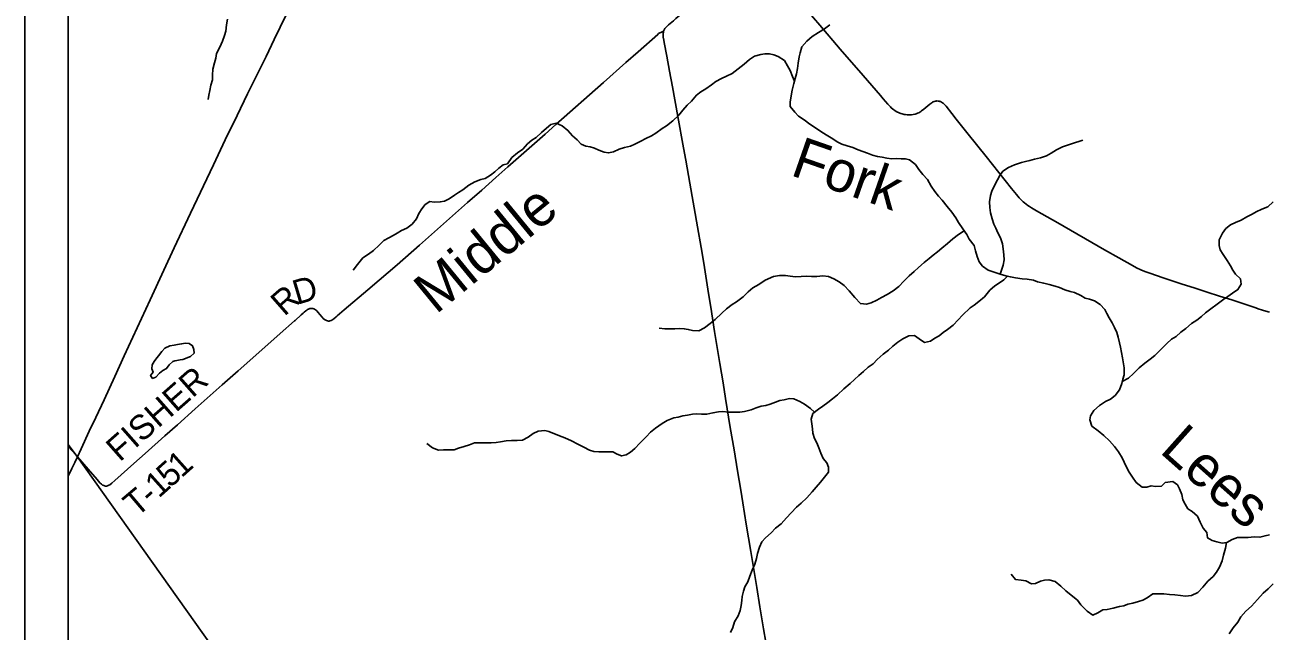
# Model space of a CAD drawing. Extents: x 0 to 34, y 0 to 22.
# Drawn here: x 2 to 4.871, y 16.697 to 18.098 of the extents above; entities that cross this region are included whole.
import ezdxf

# ---------------------------------------------------------------- set-up
doc = ezdxf.new("R2010")
doc.units = 0
for name, color, linetype in [('Default', 7, 'Continuous'), ('GM_X_County_Road', 7, 'Continuous'), ('GM_X_Minor_Lake', 7, 'Continuous'), ('GM_X_Minor_River', 7, 'Continuous'), ('GM_X_Minor_River_Text', 7, 'Continuous'), ('GM_X_State_Route', 7, 'Continuous'), ('GM_X_Township_Road', 7, 'Continuous'), ('GM_X_Township_Road_Text', 7, 'Continuous'), ('SH_Cut_Line', 7, 'Continuous'), ('SH_Data', 7, 'Continuous')]:
    doc.layers.add(name, color=color, linetype=linetype)

msp = doc.modelspace()

# ---------------------------------------------------------------- linework, layer by layer
at = {"layer": 'Default'}
msp.add_lwpolyline([(6.6858, 19.0362), (6.6949, 19.1537), (6.8302, 20.9), (3.1229, 20.9), (2.9275, 20.8467), (2.2946, 20.6707), (2.1, 20.6202), (2.1, 17.1279), (2.1211, 17.1003), (3.2076, 15.5689), (3.4902, 15.1704), (4.0558, 14.3671), (4.1658, 14.2105), (4.302, 14.3105), (5.6165, 15.2674), (6.0871, 15.6176), (6.2834, 15.7529), (6.4392, 15.8657), (6.5428, 17.1931), (6.5451, 17.2211), (6.6309, 18.3364), (6.6363, 18.3979), (6.6654, 18.7733)], dxfattribs=at)
msp.add_lwpolyline([(2.1, 17.1279), (2.1, 14.1), (4.022, 14.1), (4.1658, 14.2105), (4.0558, 14.3671), (3.4902, 15.1704), (3.2076, 15.5689), (2.1211, 17.1003)], close=True, dxfattribs=at)
at = {"layer": 'GM_X_County_Road'}
for points in [[(3.4749, 18.0827), (3.4756, 18.0847), (3.4764, 18.0862), (3.4771, 18.0877), (3.4779, 18.0888), (3.4786, 18.0899), (3.4795, 18.091), (3.4808, 18.0924), (3.4827, 18.0944), (3.4864, 18.0979), (3.4902, 18.1011), (3.4974, 18.1071), (3.5031, 18.1119), (3.5555, 18.1568), (3.5751, 18.174), (3.6216, 18.2143), (3.6711, 18.2567), (3.6866, 18.27)], [(4.8734, 17.4339), (4.8656, 17.4358), (4.8573, 17.4384), (4.8478, 17.4416), (4.842, 17.4436), (4.7865, 17.4619), (4.7586, 17.4707), (4.7297, 17.4801), (4.6996, 17.4898), (4.6724, 17.4987), (4.647, 17.507), (4.6281, 17.5132), (4.5976, 17.5236), (4.5859, 17.5279), (4.5768, 17.5316), (4.5666, 17.5363), (4.5573, 17.5412), (4.526, 17.5589), (4.4926, 17.5781), (4.3848, 17.6399), (4.3358, 17.6682), (4.3241, 17.6751), (4.32, 17.6777), (4.3158, 17.6805), (4.3119, 17.6834), (4.3084, 17.686), (4.3053, 17.6888), (4.302, 17.6918), (4.2989, 17.695), (4.296, 17.698), (4.2895, 17.7055), (4.2782, 17.7195), (4.249, 17.7566), (4.2193, 17.7933), (4.1782, 17.8447), (4.1505, 17.8798), (4.1404, 17.8924), (4.1269, 17.9095), (4.1249, 17.9118), (4.1236, 17.9133), (4.1223, 17.9147), (4.1205, 17.9163), (4.119, 17.9177), (4.1167, 17.919), (4.1144, 17.9202), (4.1129, 17.9207), (4.1113, 17.9212), (4.1088, 17.9216), (4.1055, 17.9218), (4.1038, 17.9216), (4.1023, 17.9213), (4.0998, 17.9206), (4.0974, 17.9195), (4.0959, 17.9187), (4.0942, 17.9175), (4.0897, 17.9141), (4.0758, 17.9025), (4.0705, 17.8986), (4.0689, 17.8974), (4.0665, 17.896), (4.0641, 17.8947), (4.0608, 17.8932), (4.0582, 17.8922), (4.0556, 17.8914), (4.0509, 17.8903), (4.0475, 17.8898), (4.0445, 17.8895), (4.0419, 17.8895), (4.0393, 17.8896), (4.0369, 17.8898), (4.0337, 17.8902), (4.0302, 17.8907), (4.0281, 17.8911), (4.0254, 17.8918), (4.0229, 17.8925), (4.0201, 17.8934), (4.0168, 17.8948), (4.0145, 17.8959), (4.0119, 17.8972), (4.0087, 17.8994), (4.0063, 17.901), (4.003, 17.9037), (4.0002, 17.9062), (3.9985, 17.9079), (3.9922, 17.9147), (3.9821, 17.9265), (3.9756, 17.934), (3.9359, 17.9802), (3.8827, 18.0418), (3.8358, 18.0965), (3.8061, 18.1308)], [(3.7107, 16.671), (3.7056, 16.7017), (3.6973, 16.7526), (3.6899, 16.7973), (3.6762, 16.8807), (3.6658, 16.9439), (3.6576, 16.9935), (3.6528, 17.0223), (3.6456, 17.0671), (3.6375, 17.1155), (3.6287, 17.1676), (3.6179, 17.2344), (3.6122, 17.2706), (3.6049, 17.3154), (3.5965, 17.3663), (3.5927, 17.389), (3.5887, 17.4148), (3.5854, 17.4356), (3.577, 17.4865), (3.5674, 17.5466), (3.5612, 17.5828), (3.5533, 17.6312), (3.5354, 17.7321), (3.526, 17.7847), (3.5209, 17.8135), (3.5078, 17.8856), (3.4954, 17.9541), (3.4887, 17.9907), (3.4822, 18.0249), (3.4762, 18.0567), (3.4751, 18.0622), (3.474, 18.0691), (3.4738, 18.0717), (3.4736, 18.0742), (3.4737, 18.0766), (3.4739, 18.0786), (3.4742, 18.0804), (3.4746, 18.0818), (3.4749, 18.0827)]]:
    msp.add_lwpolyline(points, dxfattribs=at)
at = {"layer": 'GM_X_Minor_Lake'}
for points in [[(2.316, 17.3428), (2.3083, 17.333), (2.3021, 17.3255), (2.2986, 17.3194), (2.294, 17.3119), (2.2935, 17.3028), (2.2964, 17.2948), (2.2902, 17.2872), (2.2947, 17.2807), (2.3024, 17.2837), (2.3105, 17.2927), (2.3182, 17.2987), (2.3273, 17.3035), (2.3335, 17.3118), (2.342, 17.3201), (2.3466, 17.321)], [(2.3466, 17.321), (2.3512, 17.3219), (2.3588, 17.3233), (2.3649, 17.3244), (2.3825, 17.331), (2.3906, 17.3393), (2.3903, 17.3473), (2.3869, 17.356), (2.3794, 17.3614), (2.371, 17.3623), (2.3619, 17.3605), (2.3527, 17.3591), (2.3444, 17.3573), (2.3348, 17.3562), (2.3233, 17.3507), (2.316, 17.3428)]]:
    msp.add_lwpolyline(points, dxfattribs=at)
at = {"layer": 'GM_X_Minor_River'}
for points in [[(2.4676, 18.1111), (2.4659, 18.0975), (2.4639, 18.0834), (2.4611, 18.0732), (2.4567, 18.06), (2.4501, 18.0464), (2.4423, 18.0316), (2.4406, 18.021), (2.4382, 18.01), (2.4343, 17.9952), (2.4333, 17.9816), (2.4336, 17.9706), (2.4292, 17.9585), (2.4268, 17.9456), (2.4248, 17.935), (2.4231, 17.9251)], [(3.8655, 17.8344), (3.8538, 17.8413), (3.8398, 17.8495), (3.8281, 17.858), (3.8126, 17.8684), (3.7994, 17.878), (3.7859, 17.8866), (3.7776, 17.8961), (3.7671, 17.9088), (3.7672, 17.9191), (3.7693, 17.9335), (3.7717, 17.9467), (3.7754, 17.9619), (3.7785, 17.9736), (3.7817, 17.9846), (3.7838, 17.9971), (3.7854, 18.0093), (3.7879, 18.0237), (3.7903, 18.0331), (3.7943, 18.0472), (3.8058, 18.0596), (3.8181, 18.0704), (3.8327, 18.0802), (3.8461, 18.0884), (3.8588, 18.0977)], [(3.7769, 17.9678), (3.7721, 17.9786), (3.767, 17.992), (3.761, 18.0031), (3.7536, 18.0153), (3.7396, 18.0246), (3.729, 18.0281), (3.7191, 18.0309), (3.7088, 18.031), (3.6993, 18.0292), (3.6848, 18.0256), (3.6729, 18.0174), (3.661, 18.0065), (3.6468, 17.9956), (3.633, 17.9855), (3.62, 17.9792), (3.6081, 17.9737), (3.5951, 17.9666), (3.5855, 17.9591), (3.5724, 17.9501), (3.5605, 17.943), (3.5506, 17.9348), (3.5394, 17.9212), (3.529, 17.9122), (3.5193, 17.9002), (3.5101, 17.8893), (3.4962, 17.8761), (3.4816, 17.8642), (3.4716, 17.8582), (3.4567, 17.847), (3.4471, 17.841), (3.4337, 17.8347), (3.4226, 17.8291), (3.4084, 17.822), (3.3985, 17.8172), (3.3844, 17.8143), (3.3721, 17.8107), (3.3591, 17.8044), (3.3477, 17.8018), (3.3374, 17.8031), (3.3253, 17.8078), (3.3155, 17.8125), (3.3056, 17.8156), (3.2954, 17.8176), (3.2844, 17.8223), (3.275, 17.8319), (3.2645, 17.8415), (3.254, 17.8538), (3.2408, 17.8646), (3.2271, 17.8704), (3.2146, 17.8675), (3.2046, 17.8589), (3.1926, 17.8488), (3.1807, 17.8375), (3.1707, 17.8308), (3.1608, 17.8229), (3.1499, 17.8105), (3.1373, 17.8019), (3.1246, 17.7911), (3.1142, 17.7767), (3.1046, 17.7738), (3.0946, 17.7663), (3.085, 17.7581), (3.075, 17.7502), (3.0628, 17.7424), (3.0528, 17.7402), (3.0391, 17.735), (3.0253, 17.7268), (3.0115, 17.7167), (3.0015, 17.71), (2.9919, 17.7037), (2.9796, 17.6958), (2.9689, 17.6902), (2.959, 17.6885), (2.9453, 17.6882), (2.935, 17.6891), (2.9243, 17.6828), (2.9166, 17.6726), (2.9096, 17.662), (2.9041, 17.6496), (2.8941, 17.6368), (2.8818, 17.6282), (2.8696, 17.6226), (2.8596, 17.6166), (2.85, 17.611), (2.8404, 17.6058), (2.8289, 17.5991), (2.8182, 17.5882), (2.8047, 17.5766), (2.7932, 17.568), (2.7805, 17.559), (2.7682, 17.544), (2.7581, 17.5308)], [(4.6331, 17.0405), (4.6243, 17.0318), (4.6102, 17.0308), (4.6007, 17.0321), (4.5908, 17.0295), (4.5801, 17.0297), (4.5658, 17.0405), (4.5572, 17.0523), (4.5501, 17.0638), (4.5445, 17.0741), (4.5382, 17.0875), (4.5334, 17.0974), (4.5248, 17.1112), (4.5158, 17.1235), (4.5042, 17.1365), (4.491, 17.1484), (4.4782, 17.1592), (4.4635, 17.1704), (4.4588, 17.1849), (4.4604, 17.1944), (4.4678, 17.2064), (4.4816, 17.2184), (4.495, 17.227), (4.5069, 17.233), (4.5173, 17.2412), (4.5273, 17.2544), (4.5328, 17.2692), (4.5352, 17.279), (4.538, 17.2889), (4.5382, 17.3052), (4.5368, 17.3147), (4.5347, 17.328), (4.5318, 17.3402), (4.5297, 17.3531), (4.5271, 17.3627), (4.5242, 17.376), (4.5213, 17.3871), (4.5157, 17.3981), (4.5102, 17.4088), (4.5035, 17.4207), (4.4983, 17.4306), (4.4934, 17.4402), (4.4825, 17.4517), (4.4697, 17.4598), (4.458, 17.4641), (4.4485, 17.4661), (4.4379, 17.472), (4.4235, 17.479), (4.4133, 17.4817), (4.4015, 17.4853), (4.3886, 17.4904), (4.3788, 17.4939), (4.3648, 17.4978), (4.3526, 17.5006), (4.3382, 17.5042), (4.3287, 17.5074), (4.3143, 17.5098), (4.3029, 17.5107), (4.287, 17.5132), (4.2756, 17.5152), (4.2646, 17.5176), (4.2517, 17.5215), (4.2358, 17.5267), (4.224, 17.531), (4.2112, 17.5402), (4.2033, 17.5498), (4.1989, 17.5624), (4.1953, 17.5757), (4.192, 17.5879), (4.1807, 17.6021), (4.1748, 17.6132), (4.1658, 17.6266), (4.1557, 17.6411), (4.1498, 17.6519), (4.1404, 17.6649), (4.1295, 17.6779), (4.1183, 17.6925), (4.1093, 17.7021), (4.101, 17.7124), (4.0928, 17.7251), (4.0843, 17.74), (4.0734, 17.7522), (4.0644, 17.7634), (4.0561, 17.7749), (4.0426, 17.786), (4.0331, 17.788), (4.0236, 17.7881), (4.0122, 17.7886), (4.0015, 17.7884), (3.9901, 17.7897), (3.9795, 17.7917), (3.9689, 17.7937), (3.9575, 17.7965), (3.9454, 17.8012), (3.9351, 17.8051), (3.9242, 17.8086), (3.9117, 17.8141), (3.8988, 17.818), (3.8866, 17.8216), (3.8757, 17.8274), (3.8655, 17.8344)], [(4.2518, 17.5215), (4.2544, 17.5283), (4.2588, 17.5427), (4.2608, 17.5549), (4.2606, 17.5663), (4.2592, 17.58), (4.2575, 17.5918), (4.2527, 17.6055), (4.2468, 17.6173), (4.2419, 17.6276), (4.2375, 17.6372), (4.2338, 17.6494), (4.2298, 17.6635), (4.2281, 17.6757), (4.2275, 17.689), (4.2299, 17.7034), (4.2327, 17.7132), (4.2405, 17.7295), (4.246, 17.7397), (4.2514, 17.7495), (4.2584, 17.7593), (4.271, 17.7683), (4.2848, 17.7742), (4.3008, 17.7793), (4.3104, 17.7822), (4.3207, 17.7844), (4.331, 17.787), (4.3451, 17.7902), (4.3592, 17.795), (4.37, 17.8009), (4.3822, 17.8092), (4.3956, 17.8155), (4.4071, 17.8199), (4.4166, 17.8228), (4.4426, 17.8309)], [(4.6371, 17.3617), (4.6472, 17.3711), (4.6579, 17.3779), (4.6694, 17.3877), (4.6808, 17.3963), (4.6938, 17.4076), (4.7061, 17.4155), (4.7164, 17.4234), (4.7263, 17.4324), (4.7385, 17.4414), (4.7527, 17.452), (4.768, 17.4636), (4.7779, 17.47), (4.7886, 17.4775), (4.8008, 17.4858), (4.8081, 17.4986), (4.8067, 17.5108), (4.7954, 17.5215), (4.789, 17.531), (4.7838, 17.5406), (4.7759, 17.5528), (4.7665, 17.5673), (4.7601, 17.5779), (4.7572, 17.5878), (4.7577, 17.6007), (4.7654, 17.6162), (4.7727, 17.6268), (4.7834, 17.6358), (4.7952, 17.6411), (4.8085, 17.6463), (4.8215, 17.6538), (4.8337, 17.6605), (4.8432, 17.6654), (4.8562, 17.6714), (4.8699, 17.677), (4.8822, 17.689)], [(4.1689, 17.622), (4.1554, 17.6134), (4.1427, 17.6029), (4.1304, 17.5924), (4.117, 17.5819), (4.107, 17.5733), (4.0974, 17.5654), (4.0878, 17.558), (4.0766, 17.5486), (4.0632, 17.5366), (4.0535, 17.5276), (4.042, 17.5174), (4.0293, 17.5051), (4.0177, 17.4934), (4.0051, 17.4833), (3.9909, 17.4747), (3.9779, 17.468), (3.9671, 17.4617), (3.9537, 17.455), (3.9434, 17.4525), (3.9294, 17.4534), (3.9162, 17.4676), (3.9035, 17.4829), (3.8918, 17.4952), (3.8805, 17.5041), (3.8677, 17.5107), (3.8552, 17.5158), (3.8423, 17.5178), (3.8289, 17.5164), (3.816, 17.5162), (3.8053, 17.5171), (3.7928, 17.5165), (3.7791, 17.5155), (3.7669, 17.5171), (3.7559, 17.5184), (3.7422, 17.5182), (3.7285, 17.5164), (3.7094, 17.5075), (3.6944, 17.4978), (3.681, 17.4896), (3.6702, 17.481), (3.6583, 17.469), (3.6433, 17.4577), (3.6334, 17.4518), (3.6199, 17.4417), (3.6091, 17.4311), (3.5937, 17.4169), (3.5822, 17.4075), (3.5692, 17.3974), (3.5558, 17.3907), (3.5417, 17.3916), (3.5318, 17.3937), (3.5223, 17.3953), (3.5117, 17.3958), (3.501, 17.3955), (3.4877, 17.3949), (3.4774, 17.3954), (3.4645, 17.3967)], [(4.2686, 17.5167), (4.2606, 17.5081), (4.2507, 17.5014), (4.2396, 17.4943), (4.228, 17.4842), (4.2157, 17.4695), (4.203, 17.4586), (4.1918, 17.4497), (4.1823, 17.4437), (4.1653, 17.4268), (4.1549, 17.4159), (4.1433, 17.4039), (4.1303, 17.3937), (4.1203, 17.3866), (4.1107, 17.3791), (4.1007, 17.3736), (4.0912, 17.3668), (4.0774, 17.3639), (4.0646, 17.3724), (4.054, 17.3802), (4.0407, 17.3788), (4.0273, 17.3725), (4.0158, 17.3646), (4.0039, 17.3553), (3.9939, 17.3463), (3.982, 17.3369), (3.9678, 17.3242), (3.9589, 17.3144), (3.947, 17.3065), (3.9362, 17.2964), (3.9255, 17.2874), (3.9155, 17.2784), (3.9054, 17.269), (3.8912, 17.2566), (3.8766, 17.2431), (3.8651, 17.2334), (3.8539, 17.2251), (3.8424, 17.2169), (3.8328, 17.2098), (3.8194, 17.1993), (3.8158, 17.1864), (3.8168, 17.1758), (3.8186, 17.1644), (3.8192, 17.1541), (3.8232, 17.1415), (3.8288, 17.1316), (3.8336, 17.1205), (3.8381, 17.1076), (3.8436, 17.0953), (3.8515, 17.0857), (3.8559, 17.0758), (3.8558, 17.0644), (3.8465, 17.0524), (3.8369, 17.0411), (3.8272, 17.0294), (3.8176, 17.0185), (3.8052, 17.005), (3.7925, 16.9922), (3.7818, 16.9828), (3.7694, 16.9697), (3.7583, 16.9588), (3.7463, 16.9449), (3.7332, 16.9347), (3.7228, 16.9242), (3.7101, 16.9126), (3.7013, 16.9028), (3.6966, 16.8911), (3.6918, 16.8763), (3.6894, 16.8646), (3.6854, 16.8517), (3.6792, 16.8373), (3.6737, 16.8241), (3.669, 16.8109), (3.6627, 16.7992), (3.6592, 16.7889), (3.6564, 16.7768), (3.6555, 16.7673), (3.6538, 16.7559), (3.6514, 16.7446), (3.6471, 16.7321), (3.6385, 16.7181), (3.635, 16.7053), (3.6291, 16.6939)], [(4.5338, 17.2732), (4.5482, 17.2811), (4.5601, 17.2924), (4.5728, 17.3048), (4.5859, 17.316), (4.5986, 17.3254), (4.6089, 17.3336), (4.6209, 17.3449), (4.6371, 17.3617)], [(3.8232, 17.2023), (3.8138, 17.2112), (3.8002, 17.2208), (3.7897, 17.2274), (3.7753, 17.2336), (3.7658, 17.2341), (3.7528, 17.2312), (3.7429, 17.2294), (3.7333, 17.2257), (3.7207, 17.2209), (3.7108, 17.2184), (3.7001, 17.2166), (3.6883, 17.2126), (3.6768, 17.2081), (3.6619, 17.2045), (3.6509, 17.2027), (3.6379, 17.2025), (3.6246, 17.203), (3.6117, 17.2039), (3.6018, 17.2033), (3.5888, 17.2008), (3.5747, 17.1983), (3.5626, 17.1984), (3.5519, 17.1989), (3.5413, 17.1979), (3.5302, 17.1961), (3.5195, 17.194), (3.5081, 17.1914), (3.4985, 17.1896), (3.4829, 17.1834), (3.4714, 17.1763), (3.456, 17.1654), (3.4449, 17.1561), (3.4345, 17.1459), (3.4202, 17.1313), (3.4087, 17.1189), (3.3983, 17.1106), (3.3887, 17.1043), (3.3776, 17.1017), (3.3678, 17.1053), (3.3572, 17.1111), (3.3469, 17.1112), (3.3367, 17.1109), (3.3249, 17.1111), (3.3138, 17.1119), (3.3036, 17.1147), (3.2907, 17.1217), (3.2764, 17.1291), (3.262, 17.1361), (3.2465, 17.1431), (3.2344, 17.1478), (3.2098, 17.158), (3.2003, 17.1607), (3.1854, 17.159), (3.1736, 17.1534), (3.1624, 17.1448), (3.1487, 17.1377), (3.1368, 17.1371), (3.1239, 17.1376), (3.111, 17.1363), (3.098, 17.1338), (3.0885, 17.1327), (3.0767, 17.1321), (3.0618, 17.1315), (3.0489, 17.132), (3.0382, 17.1318), (3.0264, 17.1273), (3.0146, 17.1237), (3.0012, 17.1193), (2.9913, 17.1156), (2.981, 17.1153), (2.9665, 17.1159), (2.9551, 17.1149), (2.9415, 17.1199), (2.9283, 17.1304)], [(4.7415, 16.9065), (4.7309, 16.9123), (4.7287, 16.9249), (4.7204, 16.9348), (4.7137, 16.9485), (4.7074, 16.9622), (4.6949, 16.9733), (4.6851, 16.9795), (4.6787, 16.9901), (4.6735, 17), (4.6713, 17.0122), (4.6661, 17.0252), (4.6612, 17.0347), (4.6503, 17.0424), (4.6331, 17.0405)], [(4.8737, 16.9192), (4.8634, 16.917), (4.8517, 16.9137), (4.838, 16.9145), (4.8243, 16.9131), (4.8103, 16.9129), (4.8, 16.9133), (4.7878, 16.9088), (4.7752, 16.9014), (4.7646, 16.9003), (4.7521, 16.9034), (4.7415, 16.9065)], [(4.7748, 16.9013), (4.7721, 16.8885), (4.7674, 16.8726), (4.7643, 16.8593), (4.7584, 16.8449), (4.7511, 16.8328), (4.7438, 16.823), (4.7312, 16.8121), (4.7197, 16.7981), (4.7086, 16.7861), (4.6937, 16.779), (4.6801, 16.7775), (4.6683, 16.7791), (4.655, 16.7804), (4.6425, 16.7816), (4.6299, 16.7833)], [(4.6299, 16.7833), (4.6152, 16.7827), (4.6042, 16.7828), (4.5915, 16.7735), (4.5812, 16.7683), (4.5716, 16.765), (4.5583, 16.7613), (4.5468, 16.7588), (4.5373, 16.7555), (4.5273, 16.7533), (4.5128, 16.7497), (4.4991, 16.7468), (4.4892, 16.7461), (4.4777, 16.7387), (4.4662, 16.7339), (4.4526, 16.7431), (4.438, 16.7574), (4.4301, 16.7685), (4.42, 16.7769), (4.4034, 16.79), (4.3917, 16.8008), (4.3789, 16.8112), (4.3645, 16.8152), (4.3542, 16.8145), (4.3447, 16.812), (4.3336, 16.8068), (4.324, 16.8058), (4.3108, 16.8131), (4.3006, 16.8148), (4.2873, 16.8164), (4.2775, 16.8287)], [(4.8819, 16.8057), (4.8704, 16.7947), (4.8593, 16.7842), (4.8463, 16.7695), (4.8321, 16.7548), (4.8188, 16.7427), (4.8073, 16.7295), (4.8003, 16.7178), (4.79, 16.7046), (4.7807, 16.6906)]]:
    msp.add_lwpolyline(points, dxfattribs=at)
at = {"layer": 'GM_X_State_Route'}
for points in [[(2.1213, 17.0997), (2.1299, 17.1181), (2.1488, 17.1586), (2.1638, 17.1907), (2.1829, 17.2312), (2.2074, 17.2849), (2.2296, 17.3329), (2.2892, 17.4621), (2.321, 17.5309), (2.3446, 17.5822), (2.3822, 17.6627), (2.4353, 17.7744), (2.4626, 17.8316), (2.4899, 17.8881), (2.5142, 17.9385), (2.531, 17.9724), (2.5568, 18.0248), (2.5755, 18.0634), (2.6031, 18.1204)], [(2.1, 17.0551), (2.1086, 17.0725), (2.1152, 17.0866), (2.1213, 17.0997)]]:
    msp.add_lwpolyline(points, dxfattribs=at)
at = {"layer": 'GM_X_Township_Road'}
for points in [[(2.1213, 17.0997), (2.1463, 17.0713), (2.167, 17.0472), (2.1734, 17.0397), (2.1769, 17.0361), (2.1788, 17.0347), (2.1794, 17.0343), (2.1802, 17.0338), (2.182, 17.0329), (2.1842, 17.0321), (2.1864, 17.0317), (2.1886, 17.0319), (2.1906, 17.0324), (2.1922, 17.033), (2.1941, 17.0337), (2.1964, 17.0351), (2.2009, 17.0386), (2.208, 17.0448), (2.2514, 17.0839), (2.2779, 17.1074), (2.3235, 17.1477), (2.3522, 17.1733), (2.3935, 17.2101), (2.4557, 17.2655), (2.4926, 17.2979), (2.5473, 17.3467), (2.5896, 17.3841), (2.6225, 17.4135), (2.6238, 17.4148), (2.6382, 17.4277), (2.6428, 17.4318), (2.6452, 17.4339), (2.6486, 17.4368), (2.6507, 17.4382), (2.6527, 17.4397), (2.6547, 17.4407), (2.6565, 17.4415), (2.6581, 17.442), (2.6598, 17.4423), (2.6618, 17.4425), (2.6636, 17.4424), (2.6648, 17.4422), (2.6669, 17.4416), (2.669, 17.4407), (2.6711, 17.4393), (2.6723, 17.4382), (2.674, 17.4368), (2.6774, 17.433), (2.6809, 17.4286), (2.6864, 17.4219), (2.689, 17.4192), (2.6918, 17.4168), (2.6933, 17.4159), (2.6948, 17.415), (2.6966, 17.4142), (2.699, 17.4135), (2.701, 17.4132), (2.7026, 17.4132), (2.7045, 17.4136), (2.707, 17.4145), (2.7091, 17.4155), (2.7111, 17.4169), (2.7136, 17.4186), (2.7188, 17.423), (2.7212, 17.425), (2.7372, 17.4388), (2.7917, 17.4851), (2.8177, 17.5073), (2.8596, 17.5433), (2.9114, 17.5888), (3.0221, 17.6868), (3.0553, 17.7158), (3.0878, 17.7448), (3.1155, 17.7697), (3.2013, 17.8453), (3.2263, 17.8676), (3.3357, 17.9643), (3.3879, 18.0103), (3.4159, 18.0349), (3.4613, 18.0755), (3.4633, 18.0774), (3.466, 18.0789), (3.4684, 18.0802), (3.4712, 18.0812), (3.4749, 18.0827)], [(2.1, 17.1235), (2.1168, 17.1048), (2.1213, 17.0997)]]:
    msp.add_lwpolyline(points, dxfattribs=at)
at = {"layer": 'SH_Cut_Line'}
msp.add_lwpolyline([(6.6858, 19.0362), (6.6949, 19.1537), (6.8302, 20.9), (2.1, 20.9), (2.1, 14.1), (4.022, 14.1), (4.1658, 14.2105), (4.302, 14.3105), (5.6165, 15.2674), (6.0871, 15.6176), (6.2834, 15.7529), (6.4392, 15.8657), (6.5428, 17.1931), (6.5451, 17.2211), (6.6309, 18.3364), (6.6363, 18.3979), (6.6654, 18.7733)], dxfattribs=at)
at = {"layer": 'SH_Data'}
for p, q in [((2, 21), (2, 14)), ((2.1, 20.9), (2.1, 14.1))]:
    msp.add_line(p, q, dxfattribs=at)

# ---------------------------------------------------------------- texts
at = {"layer": 'GM_X_Minor_River_Text'}
for s, height, rotation, p in [('Fork', 0.09469, 340.7914, (3.7649, 17.7511)), ('Middle', 0.0947, 39.3418, (2.9489, 17.4271)), ('Lees', 0.09469, 318.3265, (4.6176, 17.1111))]:
    msp.add_text(s, height=height, rotation=rotation, dxfattribs=at).set_placement(p)
at = {"layer": 'GM_X_Township_Road_Text'}
for s, height, rotation, p in [('D', 0.0568, 16.5754, (2.6285, 17.4504)), ('R', 0.0568, 41.208, (2.599, 17.4227)), ('FISHER', 0.05682, 41.3889, (2.2191, 17.0862)), ('5', 0.0568, 41.8211, (2.3353, 17.0259)), ('1', 0.0568, 41.8303, (2.3614, 17.0493)), ('1', 0.0568, 41.7351, (2.3091, 17.0026)), ('T', 0.0568, 40.2308, (2.2579, 16.9586)), ('-', 0.0568, 41.5256, (2.2914, 16.9869))]:
    msp.add_text(s, height=height, rotation=rotation, dxfattribs=at).set_placement(p)

doc.saveas('drawing.dxf')
